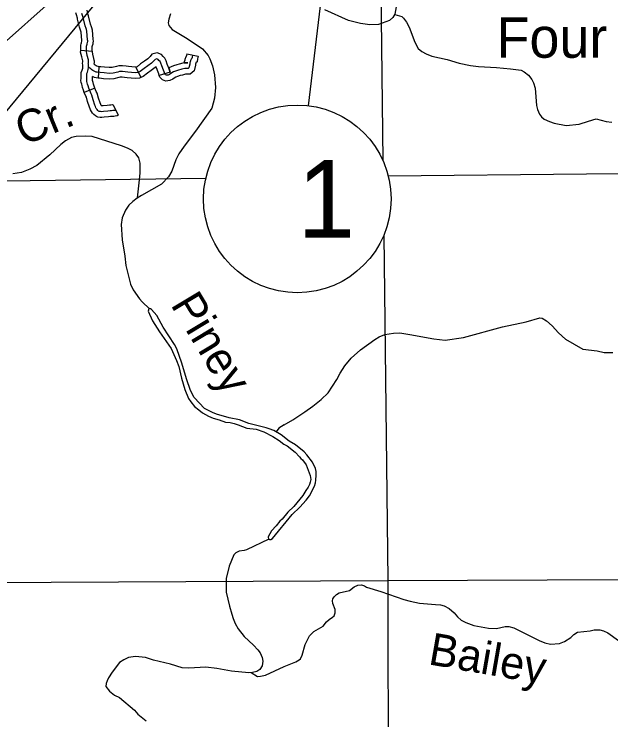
# Model space of a CAD drawing. Extents: x 1377389 to 1380723, y 1168351 to 1170484.
# Drawn here: x 1379012.3 to 1379168.8, y 1168904.3 to 1169089.4 of the extents above; entities that cross this region are included whole.
import ezdxf

# ---------------------------------------------------------------- set-up
doc = ezdxf.new("R2010")
doc.units = 0
doc.layers.add('B_Contour_Elevations', color=7, linetype='Continuous')
doc.layers.add('B_Fill', color=7, linetype='Continuous')

msp = doc.modelspace()

# ---------------------------------------------------------------- linework, layer by layer
at = {"layer": 'B_Contour_Elevations'}
for p, q in [((1379089.49, 1169065.34), (1379098.58, 1169141.03)), ((1378478.5, 1168608.3), (1379068.4, 1169134.14)), ((1378986.43, 1169035.07), (1379068.4, 1169134.14))]:
    msp.add_line(p, q, dxfattribs=at)
at = {"layer": 'B_Fill'}
for p, q in [((1379032.77, 1169079.55), (1379029.78, 1169079.81)), ((1379057.64, 1169078.98), (1379060.58, 1169078.37)), ((1379034.56, 1169075.57), (1379034.33, 1169072.58)), ((1379044.26, 1169075.43), (1379045.56, 1169072.73)), ((1379053.21, 1169074.17), (1379050.34, 1169073.29)), ((1379033.5, 1169069.94), (1379030.71, 1169068.85)), ((1379038.26, 1169065.57), (1379039.61, 1169062.89))]:
    msp.add_line(p, q, dxfattribs=at)
for points in [[(1379108.5, 1169095.91), (1379109, 1169050.98)], [(1379112.48, 1169091.29), (1379112.17, 1169089.32), (1379111.62, 1169088.44), (1379110.72, 1169087.72), (1379107.82, 1169086.67), (1379105.61, 1169086.52), (1379103.15, 1169086.92), (1379099.95, 1169087.72), (1379093.78, 1169090.5)], [(1379029.78, 1169079.81), (1379029.8, 1169080.01), (1379029.79, 1169080.77), (1379029.83, 1169081.22), (1379029.91, 1169081.55), (1379029.97, 1169081.8), (1379030.09, 1169082.34), (1379030.1, 1169082.37), (1379030.1, 1169082.41), (1379029.88, 1169084.63), (1379029.8, 1169084.91), (1379029.73, 1169085.15), (1379029.49, 1169085.9), (1379028.97, 1169088.04), (1379028.89, 1169088.29), (1379028.65, 1169089.16), (1379028.53, 1169089.65)], [(1379038.93, 1169064.23), (1379038.72, 1169064.12), (1379038.54, 1169064.06), (1379038.39, 1169064.05), (1379038.22, 1169064.05), (1379037.84, 1169064.01), (1379037.46, 1169063.98), (1379036.9, 1169063.92), (1379035.78, 1169063.8), (1379035.32, 1169063.76), (1379035, 1169063.79), (1379034.72, 1169063.81), (1379034.64, 1169063.86), (1379034.48, 1169063.93), (1379034.26, 1169064.13), (1379034.05, 1169064.35), (1379033.86, 1169064.63), (1379033.76, 1169064.83), (1379033.65, 1169065.13), (1379033.47, 1169065.51), (1379033, 1169066.88), (1379032.65, 1169068.09), (1379032.49, 1169068.42), (1379031.89, 1169069.94), (1379031.7, 1169070.56), (1379031.57, 1169071.03), (1379031.49, 1169071.34), (1379031.4, 1169071.72), (1379031.36, 1169072.04), (1379031.37, 1169072.52), (1379031.36, 1169072.96), (1379031.36, 1169073.37), (1379031.39, 1169073.75), (1379031.55, 1169074.16), (1379031.75, 1169074.81), (1379031.86, 1169075.33), (1379031.86, 1169075.62), (1379031.78, 1169076.15), (1379031.75, 1169076.32), (1379031.82, 1169076.51), (1379031.85, 1169076.73), (1379031.85, 1169076.95), (1379031.83, 1169077.09), (1379031.78, 1169077.39), (1379031.51, 1169078.49), (1379031.38, 1169079.12), (1379031.26, 1169079.5), (1379031.3, 1169079.96), (1379031.29, 1169080.71), (1379031.31, 1169080.97), (1379031.36, 1169081.19), (1379031.43, 1169081.45), (1379031.55, 1169081.97), (1379031.6, 1169082.16), (1379031.62, 1169082.31), (1379031.59, 1169082.59), (1379031.36, 1169084.9), (1379031.25, 1169085.32), (1379031.17, 1169085.59), (1379030.94, 1169086.31), (1379030.41, 1169088.46), (1379030.32, 1169088.73), (1379030.1, 1169089.54)], [(1379032.77, 1169079.55), (1379032.8, 1169079.9), (1379032.79, 1169080.65), (1379032.8, 1169080.72), (1379032.82, 1169080.84), (1379032.89, 1169081.11), (1379033, 1169081.6), (1379033.06, 1169081.83), (1379033.14, 1169082.29), (1379033.08, 1169082.76), (1379032.84, 1169085.18), (1379032.69, 1169085.73), (1379032.6, 1169086.03), (1379032.38, 1169086.72), (1379031.86, 1169088.87), (1379031.76, 1169089.17), (1379031.56, 1169089.91), (1379031.45, 1169090.36)], [(1379053.28, 1169089.39), (1379052.87, 1169088.02), (1379052.74, 1169087.03), (1379052.92, 1169086.34), (1379053.73, 1169085.36), (1379057.67, 1169082.96), (1379061.75, 1169080.22), (1379063.18, 1169078.51), (1379063.62, 1169077.6), (1379064.32, 1169075.78), (1379064.85, 1169073.41), (1379065.09, 1169070.16), (1379064.86, 1169067.29), (1379064.13, 1169064.69), (1379059.91, 1169058.69), (1379056.86, 1169054.78), (1379055.54, 1169052.77), (1379054.7, 1169051.17), (1379053.69, 1169048.15), (1379052.82, 1169046.69), (1379050.97, 1169044.81), (1379045.69, 1169041.84)], [(1379112.13, 1169089.26), (1379113.94, 1169088.76), (1379114.43, 1169088.31), (1379115.2, 1169087.23), (1379115.86, 1169085.93), (1379117.4, 1169081.96), (1379118.21, 1169080.34), (1379119.18, 1169079.53), (1379120.33, 1169078.97), (1379121.88, 1169078.37), (1379125.84, 1169077.42), (1379129, 1169076.53), (1379131.96, 1169075.86), (1379134.1, 1169075.63), (1379138.81, 1169075.39), (1379142.49, 1169075.05), (1379145.22, 1169074.63), (1379146.05, 1169074.26), (1379147.16, 1169073.35), (1379148.03, 1169072.25), (1379148.46, 1169071.31), (1379148.9, 1169069.94), (1379149.24, 1169065.43), (1379149.51, 1169064.34), (1379150.05, 1169063.15), (1379150.61, 1169062.45), (1379151.33, 1169061.85), (1379152.66, 1169061.17), (1379153.87, 1169060.79), (1379157.06, 1169060.2), (1379160.5, 1169060.51), (1379162.91, 1169061.33), (1379164.91, 1169061.87), (1379167.56, 1169061.23), (1379169, 1169061.01)], [(1379030.71, 1169068.85), (1379030.47, 1169069.45), (1379030.26, 1169070.14), (1379030.13, 1169070.63), (1379030.03, 1169070.98), (1379029.93, 1169071.45), (1379029.85, 1169071.94), (1379029.87, 1169072.52), (1379029.86, 1169072.94), (1379029.86, 1169073.44), (1379029.92, 1169074.08), (1379030.13, 1169074.65), (1379030.3, 1169075.19), (1379030.36, 1169075.48), (1379030.36, 1169075.51), (1379030.3, 1169075.93), (1379030.21, 1169076.47), (1379030.35, 1169076.84), (1379030.35, 1169076.88), (1379030.34, 1169076.9), (1379030.31, 1169077.08), (1379030.04, 1169078.15), (1379029.92, 1169078.75), (1379029.74, 1169079.34), (1379029.78, 1169079.81)], [(1379059.11, 1169078.67), (1379058.96, 1169077.95), (1379058.91, 1169077.68), (1379058.74, 1169077.56), (1379058.66, 1169077.36), (1379058.59, 1169077.18), (1379058.54, 1169077.06), (1379058.51, 1169076.89), (1379058.39, 1169076.54), (1379058.36, 1169076.24), (1379058.14, 1169075.3), (1379057.92, 1169075.1), (1379057.82, 1169075.1), (1379057.42, 1169075.1), (1379057.05, 1169075.08), (1379056.33, 1169074.9), (1379056.01, 1169074.81), (1379055.44, 1169074.66), (1379054.63, 1169074.38), (1379054.08, 1169074.19), (1379053.41, 1169073.81), (1379053.09, 1169073.54), (1379052.72, 1169073.37), (1379052.3, 1169073.32), (1379052.03, 1169073.42), (1379051.8, 1169073.64), (1379051.64, 1169074.19), (1379051.44, 1169074.64), (1379051.07, 1169075.76), (1379050.81, 1169076.47), (1379050.57, 1169076.91), (1379050.29, 1169077.23), (1379050.06, 1169077.48), (1379049.73, 1169077.61), (1379049.3, 1169077.49), (1379049.07, 1169077.21), (1379048.34, 1169076.52), (1379047.4, 1169075.82), (1379046.37, 1169075.09), (1379045.36, 1169074.29), (1379044.79, 1169074.02), (1379044.15, 1169073.96), (1379043.09, 1169074.04), (1379042.16, 1169074.12), (1379041.46, 1169074.22), (1379040.7, 1169074.33), (1379039.95, 1169074.27), (1379039.48, 1169074.18), (1379038.28, 1169073.91), (1379037.21, 1169073.83), (1379035.91, 1169073.92), (1379034.88, 1169074.04), (1379034.12, 1169074.1), (1379033.83, 1169074.18), (1379033.45, 1169074.33), (1379033.15, 1169074.46), (1379032.98, 1169074.56), (1379032.68, 1169074.78), (1379032.43, 1169074.97), (1379032.19, 1169075.17), (1379031.89, 1169075.49)], [(1379033.29, 1169076.2), (1379033.35, 1169076.64), (1379033.35, 1169077.02), (1379033.32, 1169077.29), (1379033.25, 1169077.7), (1379032.97, 1169078.82), (1379032.83, 1169079.5), (1379032.78, 1169079.66), (1379032.77, 1169079.55)], [(1379053.21, 1169074.17), (1379053.05, 1169074.7), (1379052.84, 1169075.18), (1379052.48, 1169076.26), (1379052.18, 1169077.08), (1379051.81, 1169077.77), (1379051.41, 1169078.23), (1379050.93, 1169078.76), (1379049.81, 1169079.18), (1379048.43, 1169078.82), (1379047.96, 1169078.22), (1379047.38, 1169077.67), (1379046.52, 1169077.04), (1379045.48, 1169076.29), (1379044.56, 1169075.57), (1379044.26, 1169075.43)], [(1379060.58, 1169078.37), (1379060.43, 1169077.67), (1379060.28, 1169076.81), (1379059.99, 1169076.61), (1379059.98, 1169076.53), (1379059.87, 1169076.22), (1379059.85, 1169076.01), (1379059.49, 1169074.5), (1379058.49, 1169073.6), (1379057.82, 1169073.6), (1379057.47, 1169073.6), (1379057.28, 1169073.59), (1379056.73, 1169073.46), (1379056.42, 1169073.36), (1379055.87, 1169073.22), (1379055.12, 1169072.97), (1379054.71, 1169072.82), (1379054.27, 1169072.57), (1379053.91, 1169072.27), (1379053.13, 1169071.91), (1379052.12, 1169071.79), (1379051.2, 1169072.12), (1379050.48, 1169072.84), (1379050.34, 1169073.29)], [(1379057.64, 1169078.98), (1379057.55, 1169078.55), (1379057.49, 1169078.51), (1379057.27, 1169077.92), (1379057.2, 1169077.76), (1379057.08, 1169077.45), (1379057.05, 1169077.25), (1379056.91, 1169076.86), (1379056.89, 1169076.6), (1379057.82, 1169076.6)], [(1379057.82, 1169076.6), (1379057.37, 1169076.6), (1379056.82, 1169076.57), (1379055.94, 1169076.35), (1379055.6, 1169076.25), (1379055.02, 1169076.1), (1379054.13, 1169075.8), (1379053.46, 1169075.55), (1379052.88, 1169075.24), (1379053.21, 1169074.17)], [(1379034.56, 1169075.57), (1379034.38, 1169075.58), (1379034.31, 1169075.6), (1379034.03, 1169075.72), (1379033.81, 1169075.81), (1379033.79, 1169075.82), (1379033.58, 1169075.98), (1379033.36, 1169076.14), (1379033.29, 1169076.2)], [(1379044.39, 1169075.49), (1379044.14, 1169075.47), (1379043.2, 1169075.54), (1379042.32, 1169075.61), (1379041.68, 1169075.7), (1379040.76, 1169075.84), (1379039.73, 1169075.76), (1379039.16, 1169075.64), (1379038.06, 1169075.39), (1379037.21, 1169075.33), (1379036.05, 1169075.42), (1379035.03, 1169075.53), (1379034.56, 1169075.57)], [(1379050.34, 1169073.29), (1379050.23, 1169073.67), (1379050.04, 1169074.11), (1379049.65, 1169075.26), (1379049.53, 1169075.58), (1379049.31, 1169075.36), (1379048.28, 1169074.61), (1379047.27, 1169073.89), (1379046.15, 1169073.01), (1379045.56, 1169072.73)], [(1379033.5, 1169069.94), (1379033.31, 1169070.44), (1379033.14, 1169070.99), (1379033.02, 1169071.42), (1379032.95, 1169071.69), (1379032.88, 1169071.99), (1379032.86, 1169072.13), (1379032.87, 1169072.53), (1379032.86, 1169072.96)], [(1379034.33, 1169072.58), (1379033.87, 1169072.61), (1379033.35, 1169072.75), (1379032.86, 1169072.96)], [(1379045.56, 1169072.73), (1379045.2, 1169072.55), (1379044.17, 1169072.46), (1379042.97, 1169072.55), (1379041.99, 1169072.63), (1379041.24, 1169072.73), (1379040.64, 1169072.82), (1379040.16, 1169072.79), (1379039.8, 1169072.71), (1379038.5, 1169072.42), (1379037.21, 1169072.32), (1379035.77, 1169072.43), (1379034.74, 1169072.55), (1379034.33, 1169072.58)], [(1379038.26, 1169065.57), (1379038.22, 1169065.55), (1379038.15, 1169065.55), (1379037.7, 1169065.51), (1379037.31, 1169065.47), (1379036.75, 1169065.41), (1379035.64, 1169065.29), (1379035.32, 1169065.27), (1379035.24, 1169065.27), (1379035.23, 1169065.28), (1379035.15, 1169065.4), (1379035.13, 1169065.44), (1379035.04, 1169065.7), (1379034.86, 1169066.08), (1379034.43, 1169067.33), (1379034.06, 1169068.64), (1379033.86, 1169069.03), (1379033.5, 1169069.94)], [(1379039.61, 1169062.89), (1379039.3, 1169062.73), (1379038.84, 1169062.58), (1379038.45, 1169062.55), (1379038.29, 1169062.55), (1379037.98, 1169062.52), (1379037.61, 1169062.49), (1379037.06, 1169062.43), (1379035.91, 1169062.31), (1379035.33, 1169062.26), (1379034.89, 1169062.29), (1379034.26, 1169062.34), (1379033.95, 1169062.52), (1379033.65, 1169062.66), (1379033.21, 1169063.06), (1379032.88, 1169063.41), (1379032.57, 1169063.86), (1379032.38, 1169064.23), (1379032.26, 1169064.56), (1379032.08, 1169064.95), (1379031.57, 1169066.43), (1379031.25, 1169067.55), (1379031.11, 1169067.81), (1379030.71, 1169068.85)], [(1379044.7, 1169041.22), (1379045.23, 1169045.87), (1379045.37, 1169047.76), (1379045.39, 1169050.32), (1379045.05, 1169051.69), (1379044.32, 1169052.67), (1379043.23, 1169053.6), (1379042.07, 1169054.22), (1379040.46, 1169054.83), (1379032.82, 1169057.24), (1379030.92, 1169057.38), (1379028.57, 1169057.29), (1379027.37, 1169056.97), (1379025.82, 1169056.16), (1379024.59, 1169055.18), (1379021.64, 1169052.43), (1379018.28, 1169049.71), (1379016.46, 1169048.67), (1379014.21, 1169047.8), (1379012, 1169047.49)], [(1379214.37, 1169047.94), (1379110.42, 1169046.88)], [(1379062.54, 1169046.24), (1379003.36, 1169045.45)], [(1379045.69, 1169041.84), (1379044.58, 1169041.15), (1379043.43, 1169040.25), (1379042.4, 1169039.26), (1379041.49, 1169037.93), (1379040.65, 1169035.95), (1379040.37, 1169034.18), (1379040.61, 1169030.22), (1379041.33, 1169025.86), (1379041.58, 1169023.45), (1379042.83, 1169018.52), (1379043.54, 1169017.06), (1379045.18, 1169014.75), (1379045.87, 1169013.95), (1379047.77, 1169012.14)], [(1379109.24, 1169031.4), (1379110.34, 1168940.86)], [(1379073.85, 1168982.05), (1379071.41, 1168982.96), (1379068.7, 1168983.53), (1379065.4, 1168984.49), (1379064.33, 1168984.92), (1379062.2, 1168985.94), (1379059.48, 1168988.89), (1379058.6, 1168990.71), (1379057.51, 1168993.74), (1379056.32, 1168997.86), (1379054.95, 1169001.62), (1379054.38, 1169002.75), (1379051.36, 1169007.3), (1379049.75, 1169010.37), (1379048.34, 1169011.91), (1379048.1, 1169012.1), (1379047.8, 1169012.15), (1379047.64, 1169012.06), (1379047.48, 1169011.48), (1379048.58, 1169008.93), (1379050.42, 1169006.07), (1379053.49, 1169001.7), (1379054.91, 1168998.56), (1379055.51, 1168997), (1379056.21, 1168993.88), (1379057.04, 1168990.92), (1379058.05, 1168988.63), (1379058.62, 1168987.71), (1379059.65, 1168986.5), (1379060.74, 1168985.59), (1379061.72, 1168984.8), (1379063.26, 1168983.95), (1379064.49, 1168983.46), (1379066.1, 1168983.03), (1379067.78, 1168982.43), (1379068.92, 1168982.3), (1379070.02, 1168982.05), (1379071.03, 1168981.66)], [(1379083.1, 1168981.72), (1379085.37, 1168982.99), (1379088.58, 1168985.13), (1379090.65, 1168986.55), (1379092.83, 1168988.34), (1379094.63, 1168990.1), (1379096.95, 1168993.59), (1379097.78, 1168995.24), (1379098.99, 1168997.14), (1379100.69, 1168999.15), (1379103.13, 1169001.31), (1379106.85, 1169004.1), (1379107.99, 1169004.78), (1379109.53, 1169005.35), (1379111.81, 1169005.74), (1379113.41, 1169005.77), (1379116.03, 1169005.41), (1379122.35, 1169004.22), (1379125.37, 1169003.89), (1379130.12, 1169004.56), (1379140.4, 1169007.34), (1379146.53, 1169008.71), (1379150.16, 1169009.72), (1379150.8, 1169009.66), (1379151.88, 1169008.97), (1379153.38, 1169007.62), (1379155.09, 1169005.77), (1379156.88, 1169004.12), (1379161.41, 1169001.56), (1379165.18, 1169001.06), (1379167.06, 1169000.67), (1379169.26, 1169000.62)], [(1379071.03, 1168981.66), (1379073.33, 1168980.85), (1379075.82, 1168980.52), (1379077.77, 1168979.88), (1379080.12, 1168978.64), (1379081.78, 1168977.61), (1379083, 1168976.66), (1379083.94, 1168976.14), (1379086.01, 1168974.49), (1379087.16, 1168973.34), (1379087.46, 1168972.85), (1379087.9, 1168972.47), (1379088.87, 1168971.23), (1379089.97, 1168968.43), (1379090.08, 1168967.37), (1379089.97, 1168966.68), (1379089.8, 1168966.03), (1379089.45, 1168965.34), (1379088.79, 1168964.49), (1379088.01, 1168963.15), (1379085.67, 1168960.3), (1379084.04, 1168958.75), (1379082.56, 1168956.94), (1379081.95, 1168956.41), (1379081.02, 1168955.25), (1379079.8, 1168953.93), (1379078.91, 1168952.37), (1379079.05, 1168951.75), (1379079.26, 1168951.6), (1379079.64, 1168951.62), (1379080.02, 1168951.92), (1379085.23, 1168958.14), (1379087.22, 1168960.09), (1379088.92, 1168961.97), (1379089.75, 1168963.09), (1379091.09, 1168965.63), (1379091.3, 1168966.44), (1379091.43, 1168967.15), (1379091.49, 1168968.51), (1379091.49, 1168969.42), (1379091.33, 1168970.27), (1379090.58, 1168971.86), (1379089.1, 1168973.86), (1379088.36, 1168974.63), (1379086.05, 1168976.42), (1379084.47, 1168977.39), (1379082.36, 1168979.1), (1379080.39, 1168980.18), (1379079.17, 1168980.67), (1379078.4, 1168980.93), (1379073.85, 1168982.05)], [(1379083.1, 1168981.72), (1379081.68, 1168980.84), (1379081.06, 1168979.83)], [(1379079.1, 1168951.72), (1379073.22, 1168948.95), (1379072.59, 1168948.73), (1379071.3, 1168948.55), (1379070.46, 1168948.15), (1379069.9, 1168947.59), (1379068.73, 1168944.63), (1379067.92, 1168941.41), (1379067.95, 1168937.78), (1379068.75, 1168934.11), (1379069.44, 1168932.09), (1379069.73, 1168930.92), (1379070.25, 1168929.58), (1379071.05, 1168928.21), (1379072.65, 1168926.22), (1379075.09, 1168923.94), (1379076.2, 1168922.74), (1379076.82, 1168921.93), (1379077.33, 1168920.71), (1379077.51, 1168919.77), (1379077.32, 1168918.5), (1379076.73, 1168917.54), (1379075.95, 1168917.04), (1379074.8, 1168916.75), (1379073.89, 1168916.71), (1379069.28, 1168917.09), (1379065.47, 1168917.79), (1379062.57, 1168918.2), (1379058.13, 1168917.89), (1379056.37, 1168918.03), (1379053.35, 1168918.94), (1379048.83, 1168920.01), (1379046.76, 1168920.66), (1379044.17, 1168920.97), (1379042.27, 1168920.68), (1379041.07, 1168920.11), (1379039.97, 1168919.36), (1379038, 1168916.85), (1379037.06, 1168915.38), (1379036.7, 1168914.57), (1379036.49, 1168913.9), (1379036.38, 1168913.09), (1379037.32, 1168911.83), (1379038.62, 1168910.84), (1379039.91, 1168910.2), (1379043.85, 1168906.9), (1379044.79, 1168905.86), (1379046.91, 1168904.07)], [(1379110.34, 1168940.86), (1379193.89, 1168941.27)], [(1379004.27, 1168940.35), (1379110.34, 1168940.86)], [(1379074.43, 1168916.73), (1379076.15, 1168915.75), (1379076.91, 1168915.76), (1379078.23, 1168916.08), (1379083.16, 1168918.36), (1379086.19, 1168919.59), (1379087.06, 1168920.11), (1379087.37, 1168920.36), (1379087.85, 1168921.27), (1379088.65, 1168924.11), (1379089.75, 1168926.36), (1379090.86, 1168927.49), (1379093.35, 1168928.94), (1379094.26, 1168930.03), (1379094.96, 1168930.64), (1379095.83, 1168931.24), (1379096.19, 1168931.65), (1379096.48, 1168932.41), (1379096.5, 1168933.25), (1379095.85, 1168934.81), (1379095.8, 1168935.53), (1379095.88, 1168936.05), (1379096.25, 1168936.61), (1379096.81, 1168937.23), (1379097.57, 1168937.61), (1379100.26, 1168938.23), (1379101.44, 1168939.18), (1379102.45, 1168939.67), (1379103.37, 1168939.73), (1379104.14, 1168939.52), (1379104.73, 1168939.16), (1379108.46, 1168938), (1379114.53, 1168935.9), (1379116.18, 1168935.47), (1379118.64, 1168934.96), (1379122.78, 1168934.56), (1379124.1, 1168934.52), (1379125.11, 1168934.28), (1379126.36, 1168933.57), (1379127.66, 1168932.43), (1379128.55, 1168931.32), (1379129.49, 1168930.48), (1379130.71, 1168929.83), (1379132.86, 1168929.08), (1379136.73, 1168928.35), (1379138.75, 1168928.3), (1379141.05, 1168928.84), (1379142.05, 1168928.8), (1379143.3, 1168928.5), (1379149.98, 1168925.12), (1379151.5, 1168924.55), (1379152.99, 1168924.21), (1379155.32, 1168924.39), (1379156.66, 1168924.93), (1379158.27, 1168925.96), (1379159.1, 1168926.72), (1379160.05, 1168927.34), (1379163.35, 1168927.69), (1379164.38, 1168927.91), (1379165.86, 1168927.92), (1379166.81, 1168927.7), (1379167.99, 1168927.13), (1379170.82, 1168925.13)], [(1379110.34, 1168940.86), (1379110.41, 1168883.9)]]:
    msp.add_lwpolyline(points, dxfattribs=at)
msp.add_circle((1379086.56, 1169040.91), 24.6, dxfattribs=at)

# ---------------------------------------------------------------- texts
for s, height, p in [('Four', 10.56, (1379138.81, 1169077.91)), ('1', 20.4, (1379086.56, 1169030.71))]:
    msp.add_text(s, height=height, dxfattribs=at).set_placement(p)
for s, rotation, p in [('Cr.', 22.414, (1379014.82, 1169054.79)), ('Piney', 301.0088, (1379053.2, 1169013.22)), ('Bailey', 350.1278, (1379120.67, 1168918.94))]:
    msp.add_text(s, height=8.448, rotation=rotation, dxfattribs=at).set_placement(p)

doc.saveas('drawing.dxf')
